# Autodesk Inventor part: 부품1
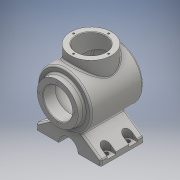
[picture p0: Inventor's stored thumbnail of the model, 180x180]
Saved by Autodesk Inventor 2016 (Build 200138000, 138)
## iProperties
Created: 2017-04
Part Number: 부품1
Material: 일반
Document SubType Name: Modeling
Designer: USER
Density: 1 g/cm^3
Appearance: 기본값
Author: USER
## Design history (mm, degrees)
sketch "스케치2"
  geometry: L1 (0, 0)-(129.011, 0); L2 (108.336, 50)-(12, 50); L3 (12, 50)-(12, 38); L4 (12, 38)-(0, 38); L5 (0, 38)-(0, 0); L6 (0, 0)-(7, 0); L7 (0, 0)-(120, 0); A1 r 113 centre (7, 0) between (120, 0) and (108.336, 50)
  constraints: 14 end point, 3 perpendicular, 2 point on circle, 1 centre point, 1 coincident, 1 collinear, 1 horizontal
  dimensions: "d0" = 12 distance of L3.end L4.end; "d2" = 7 distance of L1.start L6.end; "d3" = 226 diameter of A1; "d4" = 108 horizontal distance of L2.end L7.end; "d5" = 76 diameter of L4 L1; "d6" = 100 diameter of L2 L1
revolve "회전1" sketch "스케치2" stored, may be unused: angle "d7" = 90 deg
node "작업 평면1"
sketch "스케치3"
  geometry: L1 (50, 12)-(-50, 12) reference; C1 r 38 at (0, 62); 1 further point
  constraints: 1 centre point, 1 vertical alignment
  dimensions: "d9" = 76 diameter of C1; "d10" = 50 distance from line of C1.centre L1
extrude "돌출1" join sketch "스케치3" stored distance "d11" = 10; taper "d12" = 0 deg
node "작업 평면3"
sketch "스케치4"
  geometry: L1 (60, -82)-(-60, -82); L2 (60, -82)-(60, -72); L3 (-60, -72)-(-60, -82); L4 (-60, -72)-(-20.173, -44.113); L5 (-20.173, -44.113)-(20.173, -44.113); L6 (20.173, -44.113)-(60, -72); C1 r 50 at (0, 0) reference; 2 further points
  constraints: 12 end point, 2 horizontal, 1 midpoint, 1 parallel, 1 vertical, 1 vertical alignment
  dimensions: "d15" = 120 distance of L1.start L1.end; "d16" = 82 distance from line of L1 point (0, 0); "d17" = 10 distance of L1.start L2.end; "d18" = 10 distance of L3.start L1.end; "d21" = 55 deg angle of L2 L6; "d23" = 55 deg angle of L3 L4; "d24" = 27.88685 vertical distance of L3.start L4.end
extrude "돌출2" join sketch "스케치4" distance "d25" = 80; taper "d26" = 0 deg
node "작업 평면5"
node "작업 평면7"
  node "작업 평면6"
sketch "스케치8"
  geometry: L1 (-21.584, 20)-(-60, 20) reference; L2 (-60, 100)-(-21.584, 100) reference; L3 (60, 20)-(21.584, 20) reference; L4 (60, 20)-(60, 100) reference; L5 (21.584, 100)-(60, 100) reference; L6 (-50, 12)-(-50, 108.336) reference; L7 (-50, 32)-(-60, 32); L8 (-50, 48)-(-60, 48); L9 (-60, 32)-(-60, 48); L10 (-50, 72)-(-60, 72); L11 (-60, 88)-(-60, 72); L12 (-60, 88)-(-50, 88); A1 r 8 centre (-50, 40) between (-50, 32) and (-50, 48); A2 r 8 centre (-50, 80) between (-50, 72) and (-50, 88); 4 further points; 1 other entity
  constraints: 12 end point, 4 point on circle, 4 point on line, 3 tangent, 2 centre point, 1 vertical, 8 other
  dimensions: "d51" = 16 diameter of A1; "d52" = 20 distance from line of L1 A1.centre; "d53" = 10 dimension on A1.centre; "d54" = 16 diameter of A2; "d55" = 20 distance from line of L2 A2.centre; "d56" = 10 dimension on A2.centre; "d57" = 10 distance of L11.start L12.end
extrude "돌출3" cut sketch "스케치8" distance "d58" = 30; taper "d59" = 0 deg
sketch "스케치9"
  geometry: L1 (60, 20)-(60, 100) reference; L2 (60, 20)-(21.584, 20) reference; L3 (21.584, 100)-(60, 100) reference; L4 (50, 12)-(50, 108.336) reference; L5 (50, 32)-(60, 32); L6 (60, 32)-(60, 48); L7 (60, 48)-(50, 48); L8 (50, 72)-(60, 72); L9 (60, 72)-(60, 88); L10 (60, 88)-(50, 88); A1 r 8 centre (50, 40) between (50, 48) and (50, 32); A2 r 8 centre (50, 80) between (50, 88) and (50, 72); 3 further points
  constraints: 12 end point, 10 point on line, 4 point on circle, 2 centre point, 2 tangent
  dimensions: "d60" = 16 diameter of A1; "d61" = 16 diameter of A2; "d62" = 20 distance from line of L3 A2.centre; "d63" = 20 distance from line of L2 A1.centre; "d64" = 10 distance from line of L1 A1.centre; "d65" = 10 distance from line of L1 A2.centre; "d66" = 10 distance of L6.end L7.end; "d67" = 10 distance of L9.end L10.end
extrude "돌출4" cut sketch "스케치9" distance "d68" = 30; taper "d69" = 0 deg
sketch "스케치10"
  geometry: 2 further points
  constraints: 1 coincident
hole "구멍1" sketch "스케치10" at (0, 0) diameter "d70" = 54; stored, may be unused: countersink angle "d74" = 90 deg, drill point angle "d76" = 0 deg; dims "d71" = 6, "d72" = 4, "d73" = 2, "d75" = 22
node "작업 평면8"
fillet "모깎기1" dims "d78" = 3
sketch "스케치12"
  geometry: L1 (15, 50)-(106.454, 50) reference; L2 (12, -47)-(12, 47) reference; L3 (15, -50)-(106.454, -50) reference; L4 (25, 40)-(99.903, 40); L5 (0, 0)-(123.613, 0); L6 (0, -38)-(0, 38) reference; L7 (110, 0)-(22, 0); L8 (22, -27)-(22, 27) reference; L9 (22, 37)-(22, 0); A1 r 113 centre (7, 0) between (109.166, -48.282) and (109.166, 48.282) reference; A2 r 3 centre (106.454, 47) between (109.166, 48.282) and (106.454, 50) reference; A3 r 3 centre (15, 47) between (15, 50) and (12, 47) reference; A4 r 3 centre (15, -47) between (12, -47) and (15, -50) reference; A5 r 3 centre (106.454, -47) between (106.454, -50) and (109.166, -48.282) reference; A6 r 103 centre (7, 0) between (110, 0) and (102.69, 38.11); A7 r 3 centre (25, 37) between (25, 40) and (22, 37); A8 r 3 centre (99.903, 37) between (102.69, 38.11) and (99.903, 40)
  constraints: 8 end point, 6 point on circle, 4 tangent, 3 centre point, 1 collinear, 1 midpoint, 1 parallel, 1 perpendicular, 1 point on line
  dimensions: "d81" = 10 distance between parallel lines of L1 L4; "d83" = 10 radial gap between concentric circles of A1 A6; "d84" = 6 diameter of A7; "d85" = 6 diameter of A8
revolve "회전2" sketch "스케치12" stored, may be unused: angle "d86" = 360 deg
sketch "스케치13"
  geometry: 2 further points
  constraints: 1 vertical alignment
  dimensions: "d87" = 32.5 distance of point (0, 0) point (0, 32.5)
hole "구멍2" sketch "스케치13" at (0, 32.5) diameter "d88" = 3.242; stored, may be unused: countersink angle "d92" = 90 deg, drill point angle "d94" = 118 deg; dims "d89" = 8, "d90" = 4, "d91" = 2, "d93" = 10
node "작업 평면9"
sketch "스케치14"
  geometry: C1 r 38 at (0, 62) reference; 2 further points
  constraints: 1 coincident
hole "구멍3" sketch "스케치14" at (0, 62) diameter "d99" = 54; stored, may be unused: countersink angle "d103" = 90 deg, drill point angle "d105" = 0 deg; dims "d100" = 8, "d101" = 4, "d102" = 2, "d104" = 40
sketch "스케치15"
  geometry: C1 r 38 at (0, 62) reference; 2 further points
  constraints: 1 vertical alignment
  dimensions: "d106" = 32.5 distance of C1.centre point (0, 29.5)
hole "구멍4" sketch "스케치15" at (0, 29.5) diameter "d107" = 3.242; stored, may be unused: countersink angle "d111" = 90 deg, drill point angle "d113" = 118 deg; dims "d108" = 8, "d109" = 4, "d110" = 2, "d112" = 10
fillet "모깎기2" dims "d117" = 3
chamfer "모따기1" distance "d118" = 1; stored, may be unused: second distance "d119" = 2, angle "d120" = 45 deg
chamfer "모따기2" distance "d121" = 1; stored, may be unused: second distance "d122" = 2, angle "d123" = 45 deg
node "작업 평면10"
sketch "스케치16"
  geometry: L1 (-60, 20)-(-60, 100) reference; L2 (-60, 20)-(60, 20) reference; L3 (60, 20)-(60, 100) reference; 5 further points
  constraints: 2 vertical alignment
  dimensions: "d125" = 20 distance from line of L2 point (-50, 40); "d126" = 10 distance from line of L1 point (-50, 40); "d127" = 40 distance of point (-50, 40) point (-50, 80); "d128" = 20 distance from line of L2 point (50, 40); "d129" = 10 distance from line of L3 point (50, 40); "d130" = 40 distance of point (50, 80) point (50, 40)
hole "구멍5" sketch "스케치16" at (-50, 40), (-50, 80), (50, 80), (50, 40) diameter "d131" = 8; stored, may be unused: countersink angle "d135" = 90 deg, drill point angle "d137" = 0 deg; dims "d132" = 8, "d133" = 4, "d134" = 2, "d136" = 10
fillet "모깎기3" dims "d138" = 3
fillet "모깎기4" dims "d139" = 3
fillet "모깎기5" dims "d140" = 3
node "작업 평면11"
sketch "스케치17"
  geometry: L1 (57, -82)-(-57, -82) reference; C1 r 18 at (0, -82); 1 further point
  constraints: 1 centre point, 1 midpoint
  dimensions: "d142" = 36 diameter of C1
extrude "돌출5" cut sketch "스케치17" stored distance "d143" = 30; taper "d144" = 0 deg
node "작업 평면12"
sketch "스케치18"
  geometry: 1 further point
node "솔리드1"
pattern_circular "원형 패턴1" dims angle "d96" = 360 deg
pattern_circular "원형 패턴2" dims angle "d115" = 360 deg
other parameters: "d8" = 65, "d49" = -82, "d50" = 6, "d77" = 22, "d98" = 65, "d124" = -82
